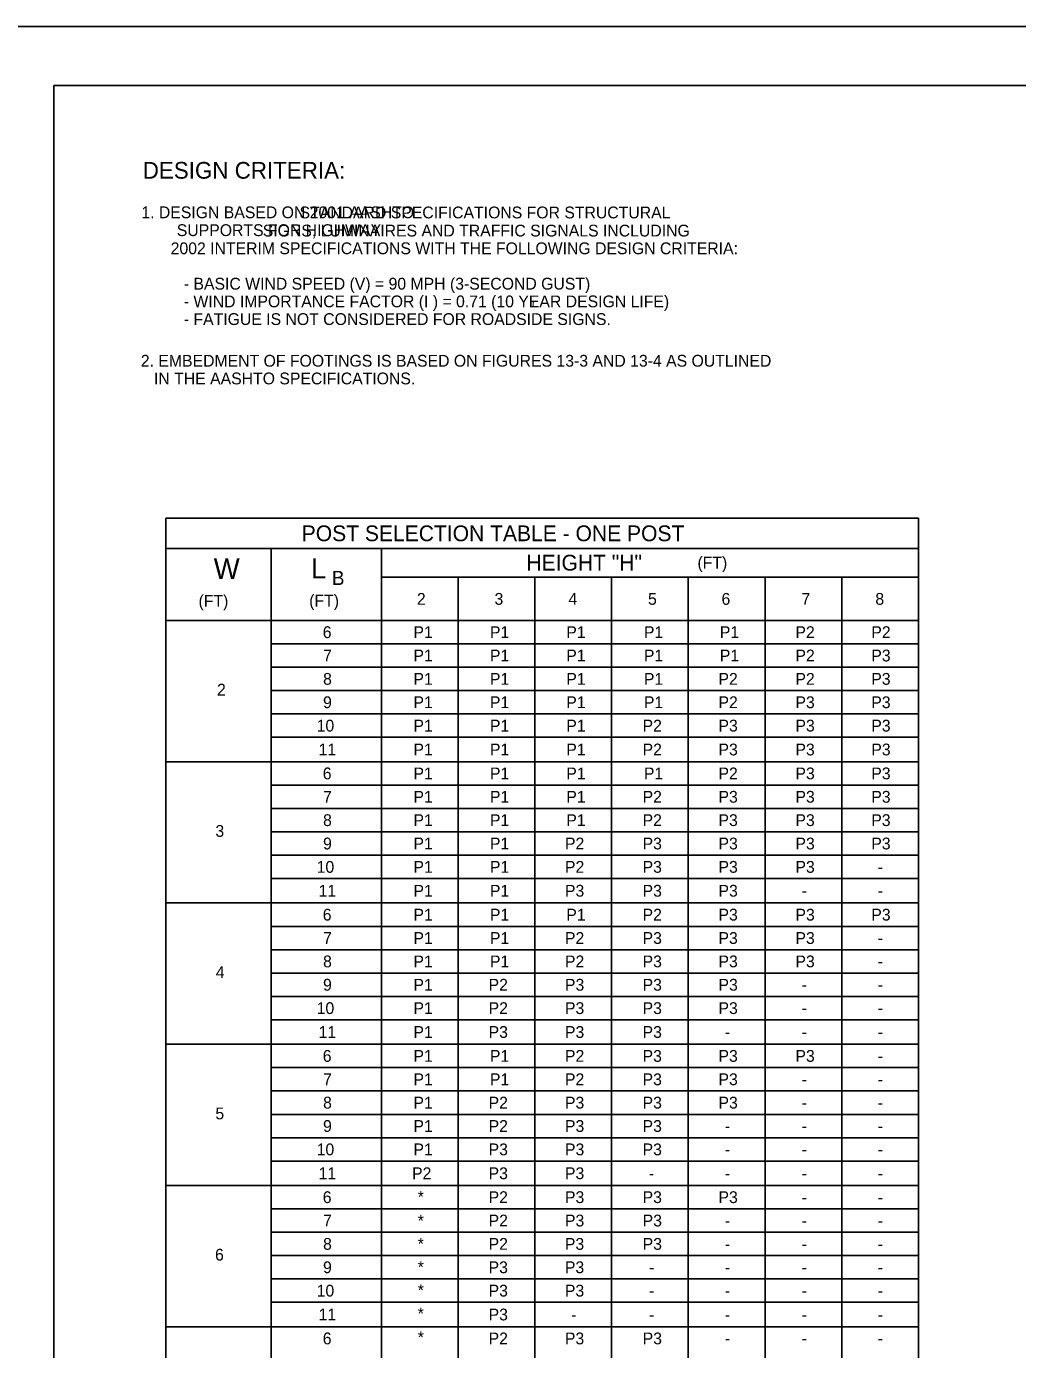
# Model space of a CAD drawing. Extents: x -2340 to 628, y -879 to 309.
# Drawn here: x -1925.3 to -1673.4, y -26.9 to 309.4 of the extents above; entities that cross this region are included whole.
import ezdxf

# ---------------------------------------------------------------- set-up
doc = ezdxf.new("R2010")
doc.units = 0
for name, color, linetype in [('Level 1', 7, 'Continuous'), ('Level 2', 7, 'Continuous'), ('PLT-BNDY', 7, 'Continuous')]:
    doc.layers.add(name, color=color, linetype=linetype)

msp = doc.modelspace()

# ---------------------------------------------------------------- linework, layer by layer
at = {"layer": 'Level 1'}
for p, q in [((-1918.39, 294.44), (-1132.39, 294.44)), ((-1918.39, 294.44), (-1918.39, -269.56)), ((-1889.94, 158.42), (-1889.94, 184.44)), ((-1889.94, 184.44), (-1698.58, 184.44)), ((-1698.58, -92.95), (-1698.58, 184.44)), ((-1889.94, 176.76), (-1835.13, 176.76)), ((-1863.14, -92.95), (-1863.14, 176.76)), ((-1835.13, -92.95), (-1835.13, 176.76)), ((-1835.13, 176.76), (-1698.58, 176.76)), ((-1815.62, 158.42), (-1815.62, 169.42)), ((-1796.12, 158.42), (-1796.12, 169.42)), ((-1776.61, 158.42), (-1776.61, 169.42)), ((-1757.1, 158.42), (-1757.1, 169.42)), ((-1737.59, 158.42), (-1737.59, 169.42)), ((-1718.09, 158.42), (-1718.09, 169.42)), ((-1889.94, 158.42), (-1698.58, 158.42))]:
    msp.add_line(p, q, dxfattribs=at)
at = {"layer": 'Level 2'}
for p, q in [((-1835.13, 169.42), (-1698.58, 169.42)), ((-1889.94, -92.95), (-1889.94, 158.42)), ((-1815.62, -92.95), (-1815.62, 158.42)), ((-1796.12, -92.95), (-1796.12, 158.42)), ((-1776.61, -92.95), (-1776.61, 158.42)), ((-1757.1, -92.95), (-1757.1, 158.42)), ((-1737.59, -92.95), (-1737.59, 158.42)), ((-1718.09, -92.95), (-1718.09, 158.42)), ((-1863.14, 152.48), (-1698.58, 152.48)), ((-1863.14, 146.54), (-1698.58, 146.54)), ((-1863.14, 140.6), (-1698.58, 140.6)), ((-1863.14, 134.66), (-1698.58, 134.66)), ((-1863.14, 128.72), (-1698.58, 128.72)), ((-1889.94, 122.51), (-1698.58, 122.51)), ((-1863.14, 116.57), (-1698.58, 116.57)), ((-1863.14, 110.63), (-1698.58, 110.63)), ((-1863.14, 104.69), (-1698.58, 104.69)), ((-1863.14, 98.75), (-1698.58, 98.75)), ((-1863.14, 92.81), (-1698.58, 92.81)), ((-1889.94, 86.6), (-1698.58, 86.6)), ((-1863.14, 80.66), (-1698.58, 80.66)), ((-1863.14, 74.72), (-1698.58, 74.72)), ((-1863.14, 68.78), (-1698.58, 68.78)), ((-1863.14, 62.84), (-1698.58, 62.84)), ((-1863.14, 56.9), (-1698.58, 56.9)), ((-1889.94, 50.69), (-1698.58, 50.69)), ((-1863.14, 44.75), (-1698.58, 44.75)), ((-1863.14, 38.81), (-1698.58, 38.81)), ((-1863.14, 32.87), (-1698.58, 32.87)), ((-1863.14, 26.93), (-1698.58, 26.93)), ((-1863.14, 20.99), (-1698.58, 20.99)), ((-1889.94, 14.78), (-1698.58, 14.78)), ((-1863.14, 8.84), (-1698.58, 8.84)), ((-1863.14, 2.9), (-1698.58, 2.9)), ((-1863.14, -3.04), (-1698.58, -3.04)), ((-1863.14, -8.98), (-1698.58, -8.98)), ((-1863.14, -14.92), (-1698.58, -14.92)), ((-1889.94, -21.13), (-1698.58, -21.13))]:
    msp.add_line(p, q, dxfattribs=at)
at = {"layer": 'PLT-BNDY'}
msp.add_lwpolyline([(-1958.39, 309.44), (-1117.39, 309.44), (-1117.39, -284.56), (-1958.39, -284.56)], close=True, dxfattribs=at)

# ---------------------------------------------------------------- texts
at = {"layer": 'Level 1'}
for s, height, p in [('1. DESIGN BASED ON 2001 AASHTO ', 3, (-1896.14, 260.69)), ('                            STANDARD SPECIFICATIONS FOR STRUCTURAL', 3, (-1887.13, 260.65)), ('SUPPORTS FOR HIGHWAY ', 3, (-1887.13, 256.15)), ('                      SIGNS, LUMINAIRES AND TRAFFIC SIGNALS INCLUDING', 3, (-1889.8, 256.04)), (' 2002 INTERIM SPECIFICATIONS WITH THE FOLLOWING DESIGN CRITERIA:', 3, (-1889.8, 251.54)), ('    - BASIC WIND SPEED (V) = 90 MPH (3-SECOND GUST)', 3, (-1889.8, 242.54)), ('    - WIND IMPORTANCE FACTOR (I ) = 0.71 (10 YEAR DESIGN LIFE)', 3, (-1889.8, 238.04)), ('r', 2, (-1796.87, 238.06)), ('    - FATIGUE IS NOT CONSIDERED FOR ROADSIDE SIGNS.', 3, (-1889.8, 233.54)), ('2. EMBEDMENT OF FOOTINGS IS BASED ON FIGURES 13-3 AND 13-4 AS OUTLINED', 3, (-1896.27, 222.95)), ('   IN THE AASHTO SPECIFICATIONS.', 3, (-1896.27, 218.45)), ('POST SELECTION TABLE - ONE POST', 4.003, (-1855.37, 178.58)), ('HEIGHT "H"', 4.003, (-1798.26, 171.11)), ('W', 5.25, (-1877.75, 168.99)), ('L', 5.16, (-1853, 169.1)), ('(FT)', 3, (-1754.77, 171.63)), ('B', 3.6, (-1847.71, 167.44)), ('(FT)', 3, (-1881.6, 161.9)), ('(FT)', 3, (-1853.47, 161.96)), ('2', 3, (-1826.1, 162.41)), ('3', 3, (-1806.36, 162.41)), ('4', 3, (-1787.58, 162.41)), ('5', 3, (-1767.34, 162.41)), ('6', 3, (-1748.65, 162.41)), ('7', 3, (-1728.33, 162.41)), ('8', 3, (-1709.55, 162.41)), ('2', 3, (-1876.91, 139.33)), ('3', 3, (-1877.31, 103.42)), ('4', 3, (-1877.22, 67.51)), ('5', 3, (-1877.31, 31.6)), ('6', 3, (-1877.4, -4.31))]:
    msp.add_text(s, height=height, dxfattribs=at).set_placement(p)
at = {"layer": 'Level 2'}
for s, height, p in [('DESIGN CRITERIA:', 4.25, (-1895.78, 270.74)), ('6', 3, (-1850.02, 153.95)), ('P1', 3, (-1826.97, 153.95)), ('P1', 3, (-1807.52, 153.95)), ('P1', 3, (-1788.11, 153.95)), ('P1', 3, (-1768.38, 153.95)), ('P1', 3, (-1749.08, 153.95)), ('P2', 3, (-1729.87, 153.95)), ('P2', 3, (-1710.58, 153.95)), ('7', 3, (-1849.94, 148.01)), ('P1', 3, (-1826.97, 148.01)), ('P1', 3, (-1807.52, 148.01)), ('P1', 3, (-1788.11, 148.01)), ('P1', 3, (-1768.38, 148.01)), ('P1', 3, (-1749.08, 148.01)), ('P2', 3, (-1729.87, 148.01)), ('P3', 3, (-1710.58, 148.01)), ('8', 3, (-1849.94, 142.07)), ('P1', 3, (-1826.97, 142.07)), ('P1', 3, (-1807.52, 142.07)), ('P1', 3, (-1788.11, 142.07)), ('P1', 3, (-1768.38, 142.07)), ('P2', 3, (-1749.43, 142.07)), ('P2', 3, (-1729.87, 142.07)), ('P3', 3, (-1710.58, 142.07)), ('9', 3, (-1849.95, 136.13)), ('P1', 3, (-1826.97, 136.13)), ('P1', 3, (-1807.52, 136.13)), ('P1', 3, (-1788.11, 136.13)), ('P1', 3, (-1768.38, 136.13)), ('P2', 3, (-1749.43, 136.13)), ('P3', 3, (-1729.87, 136.13)), ('P3', 3, (-1710.58, 136.13)), ('10', 3, (-1851.57, 130.19)), ('P1', 3, (-1826.97, 130.19)), ('P1', 3, (-1807.52, 130.19)), ('P1', 3, (-1788.11, 130.19)), ('P2', 3, (-1768.72, 130.19)), ('P3', 3, (-1749.43, 130.19)), ('P3', 3, (-1729.87, 130.19)), ('P3', 3, (-1710.58, 130.19)), ('11', 3, (-1851.09, 124.12)), ('P1', 3, (-1826.97, 124.12)), ('P1', 3, (-1807.52, 124.12)), ('P1', 3, (-1788.11, 124.12)), ('P2', 3, (-1768.72, 124.12)), ('P3', 3, (-1749.43, 124.12)), ('P3', 3, (-1729.87, 124.12)), ('P3', 3, (-1710.58, 124.12)), ('6', 3, (-1850.02, 118.04)), ('P1', 3, (-1826.97, 118.04)), ('P1', 3, (-1807.52, 118.04)), ('P1', 3, (-1788.11, 118.04)), ('P1', 3, (-1768.38, 118.04)), ('P2', 3, (-1749.43, 118.04)), ('P3', 3, (-1729.87, 118.04)), ('P3', 3, (-1710.58, 118.04)), ('7', 3, (-1849.94, 112.1)), ('P1', 3, (-1826.97, 112.1)), ('P1', 3, (-1807.52, 112.1)), ('P1', 3, (-1788.11, 112.1)), ('P2', 3, (-1768.72, 112.1)), ('P3', 3, (-1749.43, 112.1)), ('P3', 3, (-1729.87, 112.1)), ('P3', 3, (-1710.58, 112.1)), ('8', 3, (-1849.94, 106.16)), ('P1', 3, (-1826.97, 106.16)), ('P1', 3, (-1807.52, 106.16)), ('P1', 3, (-1788.11, 106.16)), ('P2', 3, (-1768.72, 106.16)), ('P3', 3, (-1749.43, 106.16)), ('P3', 3, (-1729.87, 106.16)), ('P3', 3, (-1710.58, 106.16)), ('9', 3, (-1849.95, 100.22)), ('P1', 3, (-1826.97, 100.22)), ('P1', 3, (-1807.52, 100.22)), ('P2', 3, (-1788.45, 100.22)), ('P3', 3, (-1768.72, 100.22)), ('P3', 3, (-1749.43, 100.22)), ('P3', 3, (-1729.87, 100.22)), ('P3', 3, (-1710.58, 100.22)), ('10', 3, (-1851.57, 94.28)), ('P1', 3, (-1826.97, 94.28)), ('P1', 3, (-1807.52, 94.28)), ('P2', 3, (-1788.45, 94.28)), ('P3', 3, (-1768.72, 94.28)), ('P3', 3, (-1749.43, 94.28)), ('P3', 3, (-1729.87, 94.28)), ('-', 3, (-1708.96, 94.28)), ('11', 3, (-1851.09, 88.21)), ('P1', 3, (-1826.97, 88.21)), ('P1', 3, (-1807.52, 88.21)), ('P3', 3, (-1788.45, 88.21)), ('P3', 3, (-1768.72, 88.21)), ('P3', 3, (-1749.43, 88.21)), ('-', 3, (-1728.25, 88.21)), ('-', 3, (-1708.96, 88.21)), ('6', 3, (-1850.02, 82.13)), ('P1', 3, (-1826.97, 82.13)), ('P1', 3, (-1807.52, 82.13)), ('P1', 3, (-1788.11, 82.13)), ('P2', 3, (-1768.72, 82.13)), ('P3', 3, (-1749.43, 82.13)), ('P3', 3, (-1729.87, 82.13)), ('P3', 3, (-1710.58, 82.13)), ('7', 3, (-1849.94, 76.19)), ('P1', 3, (-1826.97, 76.19)), ('P1', 3, (-1807.52, 76.19)), ('P2', 3, (-1788.45, 76.19)), ('P3', 3, (-1768.72, 76.19)), ('P3', 3, (-1749.43, 76.19)), ('P3', 3, (-1729.87, 76.19)), ('-', 3, (-1708.96, 76.19)), ('8', 3, (-1849.94, 70.25)), ('P1', 3, (-1826.97, 70.25)), ('P1', 3, (-1807.52, 70.25)), ('P2', 3, (-1788.45, 70.25)), ('P3', 3, (-1768.72, 70.25)), ('P3', 3, (-1749.43, 70.25)), ('P3', 3, (-1729.87, 70.25)), ('-', 3, (-1708.96, 70.25)), ('9', 3, (-1849.95, 64.31)), ('P1', 3, (-1826.97, 64.31)), ('P2', 3, (-1807.86, 64.31)), ('P3', 3, (-1788.45, 64.31)), ('P3', 3, (-1768.72, 64.31)), ('P3', 3, (-1749.43, 64.31)), ('-', 3, (-1728.25, 64.31)), ('-', 3, (-1708.96, 64.31)), ('10', 3, (-1851.57, 58.37)), ('P1', 3, (-1826.97, 58.37)), ('P2', 3, (-1807.86, 58.37)), ('P3', 3, (-1788.45, 58.37)), ('P3', 3, (-1768.72, 58.37)), ('P3', 3, (-1749.43, 58.37)), ('-', 3, (-1728.25, 58.37)), ('-', 3, (-1708.96, 58.37)), ('11', 3, (-1851.09, 52.3)), ('P1', 3, (-1826.97, 52.3)), ('P3', 3, (-1807.86, 52.3)), ('P3', 3, (-1788.45, 52.3)), ('P3', 3, (-1768.72, 52.3)), ('-', 3, (-1747.81, 52.3)), ('-', 3, (-1728.25, 52.3)), ('-', 3, (-1708.96, 52.3)), ('6', 3, (-1850.02, 46.22)), ('P1', 3, (-1826.97, 46.22)), ('P1', 3, (-1807.52, 46.22)), ('P2', 3, (-1788.45, 46.22)), ('P3', 3, (-1768.72, 46.22)), ('P3', 3, (-1749.43, 46.22)), ('P3', 3, (-1729.87, 46.22)), ('-', 3, (-1708.96, 46.22)), ('7', 3, (-1849.94, 40.28)), ('P1', 3, (-1826.97, 40.28)), ('P1', 3, (-1807.52, 40.28)), ('P2', 3, (-1788.45, 40.28)), ('P3', 3, (-1768.72, 40.28)), ('P3', 3, (-1749.43, 40.28)), ('-', 3, (-1728.25, 40.28)), ('-', 3, (-1708.96, 40.28)), ('8', 3, (-1849.94, 34.34)), ('P1', 3, (-1826.97, 34.34)), ('P2', 3, (-1807.86, 34.34)), ('P3', 3, (-1788.45, 34.34)), ('P3', 3, (-1768.72, 34.34)), ('P3', 3, (-1749.43, 34.34)), ('-', 3, (-1728.25, 34.34)), ('-', 3, (-1708.96, 34.34)), ('9', 3, (-1849.95, 28.4)), ('P1', 3, (-1826.97, 28.4)), ('P2', 3, (-1807.86, 28.4)), ('P3', 3, (-1788.45, 28.4)), ('P3', 3, (-1768.72, 28.4)), ('-', 3, (-1747.81, 28.4)), ('-', 3, (-1728.25, 28.4)), ('-', 3, (-1708.96, 28.4)), ('10', 3, (-1851.57, 22.46)), ('P1', 3, (-1826.97, 22.46)), ('P3', 3, (-1807.86, 22.46)), ('P3', 3, (-1788.45, 22.46)), ('P3', 3, (-1768.72, 22.46)), ('-', 3, (-1747.81, 22.46)), ('-', 3, (-1728.25, 22.46)), ('-', 3, (-1708.96, 22.46)), ('11', 3, (-1851.09, 16.39)), ('P2', 3, (-1827.32, 16.39)), ('P3', 3, (-1807.86, 16.39)), ('P3', 3, (-1788.45, 16.39)), ('-', 3, (-1767.11, 16.39)), ('-', 3, (-1747.81, 16.39)), ('-', 3, (-1728.25, 16.39)), ('-', 3, (-1708.96, 16.39)), ('6', 3, (-1850.02, 10.31)), ('*', 3, (-1825.88, 10.4)), ('P2', 3, (-1807.86, 10.31)), ('P3', 3, (-1788.45, 10.31)), ('P3', 3, (-1768.72, 10.31)), ('P3', 3, (-1749.43, 10.31)), ('-', 3, (-1728.25, 10.31)), ('-', 3, (-1708.96, 10.31)), ('7', 3, (-1849.94, 4.37)), ('*', 3, (-1825.88, 4.34)), ('P2', 3, (-1807.86, 4.37)), ('P3', 3, (-1788.45, 4.37)), ('P3', 3, (-1768.7, 4.37)), ('-', 3, (-1747.81, 4.37)), ('-', 3, (-1728.25, 4.37)), ('-', 3, (-1708.96, 4.37)), ('8', 3, (-1849.94, -1.57)), ('*', 3, (-1825.88, -1.56)), ('P2', 3, (-1807.86, -1.57)), ('P3', 3, (-1788.47, -1.57)), ('P3', 3, (-1768.7, -1.57)), ('-', 3, (-1747.81, -1.57)), ('-', 3, (-1728.25, -1.57)), ('-', 3, (-1708.96, -1.57)), ('9', 3, (-1849.95, -7.51)), ('*', 3, (-1825.88, -7.46)), ('P3', 3, (-1807.86, -7.51)), ('P3', 3, (-1788.47, -7.51)), ('-', 3, (-1767.08, -7.51)), ('-', 3, (-1747.81, -7.51)), ('-', 3, (-1728.25, -7.51)), ('-', 3, (-1708.96, -7.51)), ('10', 3, (-1851.57, -13.45)), ('*', 3, (-1825.88, -13.36)), ('P3', 3, (-1807.86, -13.45)), ('P3', 3, (-1788.47, -13.45)), ('-', 3, (-1767.08, -13.45)), ('-', 3, (-1747.81, -13.45)), ('-', 3, (-1728.25, -13.45)), ('-', 3, (-1708.96, -13.45)), ('11', 3, (-1851.09, -19.52)), ('*', 3, (-1825.88, -19.27)), ('P3', 3, (-1807.86, -19.52)), ('-', 3, (-1786.85, -19.52)), ('-', 3, (-1767.08, -19.52)), ('-', 3, (-1747.81, -19.52)), ('-', 3, (-1728.25, -19.52)), ('-', 3, (-1708.96, -19.52)), ('6', 3, (-1850.02, -25.6)), ('*', 3, (-1825.88, -25.32)), ('P2', 3, (-1807.86, -25.6)), ('P3', 3, (-1788.47, -25.6)), ('P3', 3, (-1768.7, -25.6)), ('-', 3, (-1747.81, -25.6)), ('-', 3, (-1728.25, -25.6)), ('-', 3, (-1708.96, -25.6))]:
    msp.add_text(s, height=height, dxfattribs=at).set_placement(p)

doc.saveas('drawing.dxf')
